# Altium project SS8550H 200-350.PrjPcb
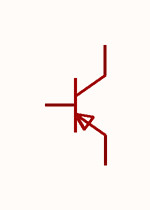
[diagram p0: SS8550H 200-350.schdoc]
1 sheet, 1 parts. Net scope: global (net labels, ports and power ports of the same name join across sheets).

## Sheet SS8550H 200-350.schdoc
size 127 x 101 mm

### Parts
Q?  ss8550(range:200-350)  [SOT-323-3_L2.0-W1.3-P1.30-LS2.1-BR]  (value not drawn)

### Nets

Not connected (* = marked no-connect by the designer): Q? 1 2 3

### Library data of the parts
Q? = ss8550(range:200-350): 晶体管类型:PNP;集电极电流(Ic):1.5A;集射极击穿电压(Vceo):25V;耗散功率(Pd):200mW;直流电流增益(hFE):200;; Manufacturer: CJ(江苏长电/长晶); Symbol: SS8550H 200-350; AddInBom: yes; ModelId: 59529c0d6fc749f28f2d0659e12986b4; ModelName: SOT-323-3_L2.0-W1.3-H1.0-LS2.1-P1.30; ModelTransform: 78.74,82.677,0,90,0,0,0.0005,0,0; type: PNP; Current - Collector(Ic): 1.5A; Collector - Emitter Voltage VCEO: 25V; Pd - Power Dissipation: 200mW; DC Current Gain: 200; Transition frequency(fT): 100MHz; Current - Collector Cutoff: 100nA; Vce Saturation(VCE(sat)): 500mV; Emitter-Base Voltage(Vebo): 5V; Number: 1个PNP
